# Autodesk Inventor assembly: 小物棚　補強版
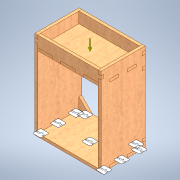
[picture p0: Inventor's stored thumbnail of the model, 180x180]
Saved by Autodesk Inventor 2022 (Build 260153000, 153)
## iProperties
Created: 2024-12
Part Number: 小物棚　補強版
Document SubType Name: Assembly
Designer: shimizu
Mass: 24.2 g
Surface Area: 281.014 cm^2
Volume: 30.25 cm^3
Density: 0.8 g/cm^3
Author: shimizu
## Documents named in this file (6)
- C:\Users\shimizu\Documents\卒論2024\3DCAD\小物棚 - 補強版\組立図\小物棚　補強版.iam
- C:\Users\shimizu\Documents\卒論2024\3DCAD\小物棚 - 補強版\部品図\底板.ipt
- C:\Users\shimizu\Documents\卒論2024\3DCAD\小物棚 - 補強版\部品図\側板.ipt
- C:\Users\shimizu\Documents\卒論2024\3DCAD\小物棚 - 補強版\部品図\天板.ipt
- C:\Users\shimizu\Documents\卒論2024\3DCAD\小物棚 - 補強版\部品図\側板②.ipt
- C:\Users\shimizu\Documents\卒論2024\3DCAD\小物棚 - 補強版\部品図\補強.ipt
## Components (10 placed, 5 different names)
1. 底板:1 — メイト:1, フラッシュ:1, フラッシュ:2, メイト:2, フラッシュ:3, フラッシュ:4, フラッシュ:13, フラッシュ:16
2. 側板:1 — メイト:2, フラッシュ:3, フラッシュ:4, メイト:4, フラッシュ:7, フラッシュ:9, メイト:8, フラッシュ:12, メイト:11, フラッシュ:15
3. 側板:2 — メイト:1, フラッシュ:1, フラッシュ:2, フラッシュ:5, フラッシュ:6, メイト:3, フラッシュ:8, フラッシュ:10, メイト:6, フラッシュ:11, メイト:10, フラッシュ:14
4. 天板:1 — フラッシュ:5, フラッシュ:6, メイト:3, メイト:5
5. 側板②:1 — メイト:4, フラッシュ:7, フラッシュ:8
6. 側板②:2 — メイト:5, フラッシュ:9, フラッシュ:10, メイト:7, メイト:9
7. 補強:1 — メイト:6, フラッシュ:11, メイト:7
8. 補強:2 — メイト:10, フラッシュ:13, フラッシュ:14
9. 補強:3 — メイト:11, フラッシュ:15, フラッシュ:16
10. 補強:4 — メイト:8, フラッシュ:12, メイト:9
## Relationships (27: Flush 16, Mate 11)
- メイト:1 [Mate]: 底板:1 ↔ 側板:2
- フラッシュ:1 [Flush]: 底板:1 ↔ 側板:2
- フラッシュ:2 [Flush]: 底板:1 ↔ 側板:2
- メイト:2 [Mate]: 底板:1 ↔ 側板:1
- フラッシュ:3 [Flush]: 底板:1 ↔ 側板:1
- フラッシュ:4 [Flush]: 底板:1 ↔ 側板:1
- フラッシュ:5 [Flush]: 側板:2 ↔ 天板:1
- フラッシュ:6 [Flush]: 側板:2 ↔ 天板:1
- メイト:3 [Mate]: 側板:2 ↔ 天板:1
- メイト:4 [Mate]: 側板:1 ↔ 側板②:1
- フラッシュ:7 [Flush]: 側板:1 ↔ 側板②:1
- フラッシュ:8 [Flush]: 側板:2 ↔ 側板②:1
- メイト:5 [Mate]: 天板:1 ↔ 側板②:2
- フラッシュ:9 [Flush]: 側板:1 ↔ 側板②:2
- フラッシュ:10 [Flush]: 側板:2 ↔ 側板②:2
- メイト:6 [Mate]: 側板:2 ↔ 補強:1
- フラッシュ:11 [Flush]: 側板:2 ↔ 補強:1
- メイト:7 [Mate]: 側板②:2 ↔ 補強:1
- メイト:8 [Mate]: 側板:1 ↔ 補強:4
- フラッシュ:12 [Flush]: 側板:1 ↔ 補強:4
- メイト:9 [Mate]: 側板②:2 ↔ 補強:4
- メイト:10 [Mate]: 側板:2 ↔ 補強:2
- フラッシュ:13 [Flush]: 底板:1 ↔ 補強:2
- フラッシュ:14 [Flush]: 側板:2 ↔ 補強:2
- メイト:11 [Mate]: 側板:1 ↔ 補強:3
- フラッシュ:15 [Flush]: 側板:1 ↔ 補強:3
- フラッシュ:16 [Flush]: 底板:1 ↔ 補強:3
## Named parameters: sa_0 = 250000 mm
